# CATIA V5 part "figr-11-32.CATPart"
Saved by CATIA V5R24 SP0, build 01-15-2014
Part number: Part1
Bounding box of the stored display mesh (mm): x -280 to 270, y -160 to 10, z 0 to 443
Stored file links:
  D:\KAVITA\CATIA V5-6R2014 Project_ Kavita\CATIA V5-6R2014_partfiles\Partfiles\c11_catia_v5-6r2014_prt\figr-11-32.CATPart
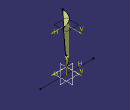
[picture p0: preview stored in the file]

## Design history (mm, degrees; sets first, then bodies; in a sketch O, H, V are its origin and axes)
Set1
  Plane1: type Offset, RefPlane xy-plane, Offset 443
  Sketch1 on Plane1, origin (0, 0, 443), H (1, 0, 0), V (0, 1, 0)
    arc A1 centre (51.3551, -160.9813) radius 171.358 from (40, 10) to (-120, -160) ccw
  Loft1: Sections (Sketch3; Sketch1)
  Sketch2 on zx-plane, origin (0, 0, 0), H (-1, 0, 0), V (0, 0, 1)
    line L1 (-270, 0) -> (280, 0)
    point P1 (-270, 0)
    coincidence: P1 H
    horizontal: L1 H
Body1 (main body)
  Sketch3 on Plane2, origin (0, 0, 67), H (1, 0, 0), V (0, 1, 0)
    point P1 (-100, 0)
    arc A1 centre (50, -150) radius 158.1139 from (0, 0) to (-100, -100) ccw
Set2
  Plane2: type Offset, RefPlane xy-plane, Offset 67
